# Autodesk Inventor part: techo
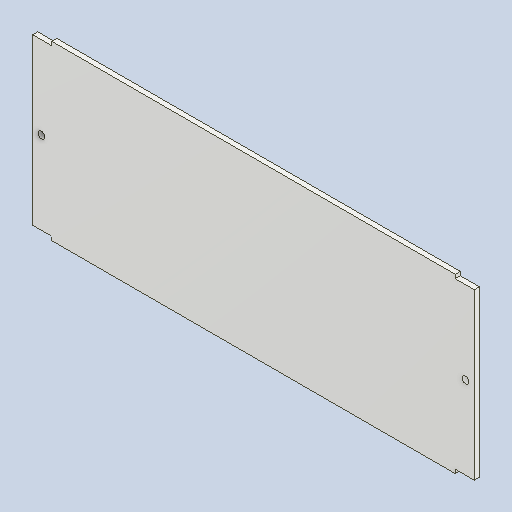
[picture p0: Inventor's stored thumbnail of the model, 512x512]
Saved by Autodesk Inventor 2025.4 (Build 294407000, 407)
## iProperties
Created: 2026-06
Part Number: techo
Material: Generic
Document SubType Name: Modeling
Designer: AdminForWorker
Density: 1 g/cm^3
Appearance: Default
Title: techo
Author: AdminForWorker
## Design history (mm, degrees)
feature "techo"
body "Solid1"
